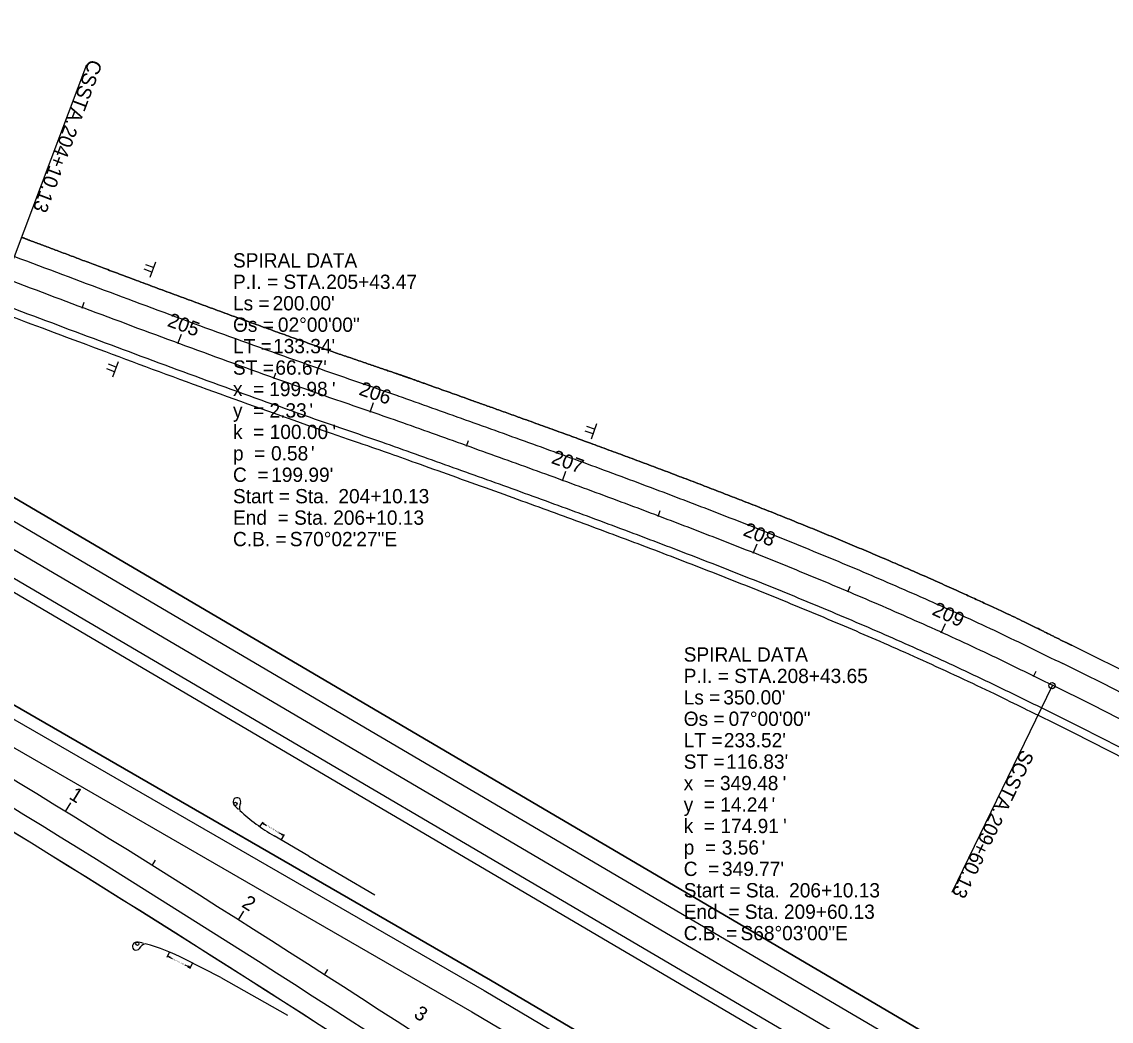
# Model space of a CAD drawing. Extents: x 76539 to 88870, y 518807 to 527554.
# Drawn here: x 86434 to 86968, y 523086 to 523575 of the extents above; entities that cross this region are included whole.
import ezdxf

# ---------------------------------------------------------------- set-up
doc = ezdxf.new("R2010")
doc.units = 0
for name, color, linetype in [('Default', 7, 'Continuous'), ('GE_P_Alignment_100_Cardinal_Points', 7, 'Continuous'), ('GE_P_Alignment_100_Curve_Data', 7, 'Continuous'), ('GE_P_Alignment_100_Stations', 7, 'Continuous'), ('PM_P_Channelizing_Line', 7, 'Continuous'), ('PM_P_Edge_Line', 7, 'Continuous'), ('PM_P_Lane_Line', 7, 'Continuous'), ('PV_P_Shoulder', 7, 'Continuous'), ('RD_P_GR_Lt', 7, 'Continuous'), ('RD_P_GR_Rt', 7, 'Continuous'), ('SC_Scratch1', 7, 'Continuous'), ('SN_P_Signs', 7, 'Continuous'), ('XS_P_Pavt_Surface', 7, 'Continuous')]:
    doc.layers.add(name, color=color, linetype=linetype)

msp = doc.modelspace()

# ---------------------------------------------------------------- linework, layer by layer
at = {"layer": 'Default'}
for points, degree in [([(86434.29, 523469.66), (86442.89, 523466.42), (86474.56, 523454.49), (86527.69, 523434.72), (86580.89, 523415.49), (86612.89, 523404.64), (86621.59, 523401.64)], 2), ([(86430.77, 523460.3), (86446.36, 523454.43), (86477.52, 523442.7), (86524.32, 523425.33), (86571.2, 523408.33), (86602.64, 523397.56), (86618.35, 523392.18)], 3), ([(86426.66, 523449.38), (86442.25, 523443.51), (86473.45, 523431.77), (86520.32, 523414.37), (86567.33, 523397.33), (86598.86, 523386.52), (86614.62, 523381.12)], 3), ([(86421.2, 523433.99), (86429.83, 523430.74), (86461.56, 523418.78), (86514.82, 523398.96), (86568.35, 523379.62), (86600.51, 523368.71), (86609.22, 523365.71)], 3), ([(86621.9, 523401.53), (86628.17, 523399.29), (86649.89, 523391.56), (86689.46, 523377.35), (86720.79, 523365.92), (86754.24, 523353.44), (86787.04, 523340.83), (86819.71, 523327.82), (86852.75, 523314.08), (86883.42, 523300.75), (86921.88, 523283.11), (86942.6, 523272.75), (86948.57, 523269.84)], 2), ([(86618.54, 523392.11), (86629.54, 523388.19), (86651.54, 523380.35), (86684.52, 523368.5), (86717.47, 523356.49), (86750.36, 523344.22), (86783.15, 523331.62), (86815.82, 523318.61), (86848.32, 523305.11), (86880.6, 523291.03), (86912.61, 523276.39), (86933.65, 523266.04), (86944.15, 523260.87)], 3), ([(86614.63, 523381.12), (86625.62, 523377.2), (86647.6, 523369.37), (86680.54, 523357.54), (86713.42, 523345.54), (86746.22, 523333.31), (86778.89, 523320.76), (86811.41, 523307.8), (86843.74, 523294.38), (86875.83, 523280.39), (86907.67, 523265.83), (86928.61, 523255.52), (86939.07, 523250.36)], 3), ([(86609.22, 523365.71), (86615.44, 523363.49), (86636.98, 523355.82), (86676.16, 523341.76), (86707.16, 523330.44), (86740.23, 523318.11), (86772.63, 523305.67), (86804.87, 523292.84), (86837.43, 523279.3), (86867.67, 523266.17), (86905.43, 523248.86), (86925.84, 523238.64), (86931.79, 523235.75)], 3)]:
    msp.add_open_spline(points, degree=degree, dxfattribs=at)
at = {"layer": 'GE_P_Alignment_100_Cardinal_Points'}
for p, q in [((86426.54, 523449.07), (86466.17, 523554.36)), ((86938.93, 523250.06), (86889.8, 523148.86))]:
    msp.add_line(p, q, dxfattribs=at)
msp.add_circle((86938.93, 523250.06), 1.5, dxfattribs=at)
at = {"layer": 'GE_P_Alignment_100_Stations'}
for p, q in [((86463.86, 523435.04), (86464.91, 523437.85)), ((86510.72, 523417.61), (86512.45, 523422.3)), ((86557.72, 523400.55), (86558.73, 523403.37)), ((86604.92, 523384.06), (86606.53, 523388.79)), ((86652.06, 523367.4), (86653.08, 523370.22)), ((86699.09, 523350.41), (86700.8, 523355.1)), ((86745.96, 523332.99), (86747.02, 523335.8)), ((86792.58, 523314.93), (86794.42, 523319.57)), ((86838.85, 523295.98), (86840.02, 523298.74)), ((86884.65, 523275.93), (86886.72, 523280.49)), ((86929.86, 523254.57), (86931.18, 523257.26)), ((86455.66, 523188.45), (86458.29, 523192.71)), ((86498.11, 523162.04), (86499.71, 523164.58)), ((86540.42, 523135.38), (86543.09, 523139.61)), ((86582.57, 523108.49), (86584.19, 523111.01))]:
    msp.add_line(p, q, dxfattribs=at)
at = {"layer": 'PM_P_Channelizing_Line'}
msp.add_arc((81834.27, 515713.3), 8788.35, 54.569749, 58.926203, dxfattribs=at)
at = {"layer": 'PM_P_Edge_Line'}
for p, q in [((86028.65, 523566.61), (87281.21, 522830.81)), ((86016.49, 523545.92), (87269.05, 522810.12)), ((86618.35, 523392.18), (86618.49, 523392.13)), ((86618.35, 523392.18), (86618.49, 523392.13)), ((86618.49, 523392.13), (86618.54, 523392.11)), ((86618.49, 523392.13), (86618.54, 523392.11)), ((86382.45, 523261.25), (86660.77, 523100.7)), ((86944.15, 523260.87), (86944.17, 523260.86)), ((86944.15, 523260.87), (86944.17, 523260.86)), ((86660.77, 523100.7), (86962.34, 522923.05))]:
    msp.add_line(p, q, dxfattribs=at)
for centre, radius, start, end in [((86313.45, 521961.45), 1444.39, 9.23728, 64.10866), ((86313.45, 521961.45), 1444.39, 9.23728, 64.10866), ((86313.45, 521961.45), 1420.39, 9.24998, 64.10866), ((81834.27, 515713.3), 8776.35, 54.569749, 58.926203)]:
    msp.add_arc(centre, radius, start, end, dxfattribs=at)
for points in [[(86430.77, 523460.3), (86446.36, 523454.43), (86477.52, 523442.7), (86524.32, 523425.33), (86571.2, 523408.33), (86602.64, 523397.56), (86618.35, 523392.18)], [(86422.53, 523437.76), (86438.06, 523431.91), (86469.22, 523420.18), (86516.1, 523402.79), (86563.18, 523385.71), (86594.77, 523374.89), (86610.54, 523369.48)], [(86618.54, 523392.11), (86629.54, 523388.19), (86651.54, 523380.35), (86684.52, 523368.5), (86717.47, 523356.49), (86750.36, 523344.22), (86783.15, 523331.62), (86815.82, 523318.61), (86848.32, 523305.11), (86880.6, 523291.03), (86912.61, 523276.39), (86933.65, 523266.04), (86944.15, 523260.87)], [(86610.54, 523369.48), (86621.51, 523365.57), (86643.45, 523357.75), (86676.33, 523345.94), (86709.14, 523333.98), (86741.84, 523321.78), (86774.39, 523309.27), (86806.76, 523296.38), (86838.9, 523283.03), (86870.79, 523269.13), (86902.39, 523254.68), (86923.17, 523244.45), (86933.55, 523239.34)]]:
    msp.add_open_spline(points, degree=3, dxfattribs=at)
at = {"layer": 'PM_P_Lane_Line'}
for p, q in [((86022.57, 523556.26), (87275.13, 522820.47)), ((86614.62, 523381.12), (86614.63, 523381.12)), ((86614.63, 523381.12), (86614.63, 523381.12)), ((86376.45, 523250.86), (86654.78, 523090.3)), ((86939.07, 523250.36), (86939.07, 523250.36)), ((86654.68, 523090.36), (86956.25, 522912.71))]:
    msp.add_line(p, q, dxfattribs=at)
msp.add_arc((86313.45, 521961.45), 1432.72, 9.23728, 64.10866, dxfattribs=at)
at = {"layer": 'PV_P_Shoulder'}
for p, q in [((86033.71, 523575.23), (87286.27, 522839.43)), ((86013.45, 523540.74), (87266.01, 522804.95)), ((86621.59, 523401.64), (86621.79, 523401.57)), ((86621.79, 523401.57), (86621.9, 523401.53)), ((86948.46, 523269.89), (86948.54, 523269.86)), ((86385.49, 523266.43), (86663.82, 523105.87)), ((86663.82, 523105.87), (86965.39, 522928.22))]:
    msp.add_line(p, q, dxfattribs=at)
for centre, radius, start, end in [((86313.45, 521961.45), 1454.39, 32.40267, 64.10866), ((86313.45, 521961.45), 1416.39, 39.00003, 64.10866), ((81834.27, 515713.3), 8766.35, 54.569749, 58.926203)]:
    msp.add_arc(centre, radius, start, end, dxfattribs=at)
at = {"layer": 'RD_P_GR_Lt'}
for p, q in [((86574.85, 523166.55), (86607.18, 523147.56)), ((86531.78, 523107.12), (86514.2, 523116.12))]:
    msp.add_line(p, q, dxfattribs=at)
msp.add_arc((86468.4, 523026.66), 100.51, 62.8901, 74.7951, dxfattribs=at)
at = {"layer": 'RD_P_GR_Rt'}
for p, q in [((86574.85, 523166.55), (86557.83, 523176.55)), ((86531.78, 523107.12), (86564.4, 523088.63))]:
    msp.add_line(p, q, dxfattribs=at)
for centre in [(86538.94, 523192.17), (86490.89, 523123.67)]:
    msp.add_circle(centre, 0.79, dxfattribs=at)
msp.add_arc((86608.74, 523263.21), 100.51, 227.6605, 239.5655, dxfattribs=at)
for centre, major_axis, start_param, end_param in [((86539.64, 523193.24), (0.89, 1.78), 4.797576, 8.898127), ((86546.34, 523190.5), (-2.53, -5.11), 4.770091, 5.435472), ((86546.38, 523198), (-4.61, -9.29), 5.763289, 6.120658), ((86490.37, 523122.51), (-1.03, -1.71), 3.668244, 7.768795), ((86489.96, 523114.27), (5.36, 8.87), 0.162527, 0.519896), ((86496.27, 523118.33), (2.95, 4.88), 0.847713, 1.513095)]:
    msp.add_ellipse(centre, major_axis=major_axis, ratio=0.944544, start_param=start_param, end_param=end_param, dxfattribs=at)
at = {"layer": 'SC_Scratch1'}
for p, q in [((86552.34, 523183.3), (86550.78, 523181.1)), ((86552.05, 523182.89), (86552.85, 523182.18)), ((86553.06, 523182.54), (86552.05, 523182.89)), ((86552.85, 523182.18), (86553.06, 523182.54)), ((86552.95, 523182.36), (86554.23, 523181.62)), ((86561.76, 523177.19), (86560.27, 523178.07)), ((86561.38, 523174.47), (86562.95, 523177.15)), ((86561.66, 523177.01), (86561.87, 523177.37)), ((86562.66, 523176.66), (86561.66, 523177.01)), ((86561.87, 523177.37), (86562.66, 523176.66)), ((86505.56, 523117.13), (86506.59, 523119.63)), ((86505.75, 523117.59), (86506.78, 523117.3)), ((86506.59, 523116.93), (86505.75, 523117.59)), ((86506.78, 523117.3), (86506.59, 523116.93)), ((86506.68, 523117.11), (86508, 523116.44)), ((86515.78, 523112.46), (86514.24, 523113.25)), ((86515.87, 523112.65), (86515.68, 523112.27)), ((86515.68, 523112.27), (86516.71, 523111.98)), ((86516.71, 523111.98), (86515.87, 523112.65)), ((86517.87, 523114.24), (86516.45, 523111.47))]:
    msp.add_line(p, q, dxfattribs=at)
at = {"layer": 'SN_P_Signs'}
for p, q in [((86497.98, 523452.62), (86494.23, 523454.03)), ((86498.82, 523454.87), (86495.08, 523456.27)), ((86499.81, 523457.49), (86497, 523450)), ((86498.4, 523453.74), (86498.4, 523453.74)), ((86480.51, 523406.08), (86476.77, 523407.49)), ((86481.49, 523408.71), (86478.68, 523401.22)), ((86479.67, 523403.84), (86475.92, 523405.24)), ((86480.09, 523404.96), (86480.09, 523404.96)), ((86714.09, 523373.44), (86710.31, 523374.75)), ((86714.87, 523375.71), (86711.09, 523377.01)), ((86715.79, 523378.35), (86713.17, 523370.79)), ((86714.48, 523374.57), (86714.48, 523374.57)), ((86714.48, 523374.57), (86714.48, 523374.57))]:
    msp.add_line(p, q, dxfattribs=at)
at = {"layer": 'XS_P_Pavt_Surface'}
for p, q in [((87286.27, 522839.43), (86033.71, 523575.23)), ((86013.45, 523540.74), (87266.01, 522804.95)), ((86663.82, 523105.87), (86385.49, 523266.43)), ((86962.55, 522929.89), (86663.82, 523105.87))]:
    msp.add_line(p, q, dxfattribs=at)
for centre, radius, start, end in [((86313.45, 521961.45), 1454.39, 32.40267, 64.10866), ((86313.45, 521961.45), 1416.39, 39.00003, 64.10866), ((81834.27, 515713.3), 8766.35, 54.568901, 58.925818)]:
    msp.add_arc(centre, radius, start, end, dxfattribs=at)
for points, degree in [([(86621.59, 523401.64), (86612.89, 523404.64), (86580.89, 523415.49), (86527.69, 523434.72), (86474.56, 523454.49), (86442.89, 523466.42), (86434.29, 523469.66)], 2), ([(86421.2, 523433.99), (86429.83, 523430.74), (86461.56, 523418.78), (86514.82, 523398.96), (86568.35, 523379.62), (86600.51, 523368.71), (86609.22, 523365.71)], 3), ([(86948.57, 523269.84), (86942.6, 523272.75), (86921.88, 523283.11), (86883.42, 523300.75), (86852.75, 523314.08), (86819.71, 523327.82), (86787.04, 523340.83), (86754.24, 523353.44), (86720.79, 523365.92), (86689.46, 523377.35), (86649.89, 523391.56), (86628.17, 523399.29), (86621.9, 523401.53)], 2), ([(86609.22, 523365.71), (86615.44, 523363.49), (86636.98, 523355.82), (86676.16, 523341.76), (86707.16, 523330.44), (86740.23, 523318.11), (86772.63, 523305.67), (86804.87, 523292.84), (86837.43, 523279.3), (86867.67, 523266.17), (86905.43, 523248.86), (86925.84, 523238.64), (86931.79, 523235.75)], 3)]:
    msp.add_open_spline(points, degree=degree, dxfattribs=at)

# ---------------------------------------------------------------- texts
at = {"layer": 'GE_P_Alignment_100_Cardinal_Points'}
for s, rotation, p in [('CS', 249.3741, (86467.39, 523557.31)), (' STA. ', 249.3741, (86463.6, 523547.24)), ('204+10.13', 249.3741, (86455.28, 523525.13)), ('SC', 244.1087, (86924.04, 523219.15)), (' STA. ', 244.1087, (86919.34, 523209.47)), ('209+60.13', 244.1087, (86909.03, 523188.22))]:
    msp.add_text(s, height=7, rotation=rotation, dxfattribs=at).set_placement(p)
at = {"layer": 'GE_P_Alignment_100_Curve_Data'}
for s, p in [('SPIRAL DATA', (86537.73, 523454.89)), ('P.I. = STA. ', (86537.73, 523444.39)), ('205+43.47', (86583.4, 523444.39)), ('Ls = ', (86537.73, 523433.89)), ("200.00'", (86557.13, 523433.89)), ('Θs = ', (86537.73, 523423.39)), ('02°00\'00"', (86559.74, 523423.39)), ('LT = ', (86537.73, 523412.89)), ("133.34'", (86557.36, 523412.89)), ('ST = ', (86537.73, 523402.39)), ("66.67'", (86558.5, 523402.39)), ('x  = ', (86537.73, 523391.89)), ('199.98', (86555.48, 523391.89)), ("'", (86586.2, 523391.89)), ('y  = ', (86537.73, 523381.39)), ('2.33', (86555.63, 523381.39)), ("'", (86575.18, 523381.39)), ('k  = ', (86537.73, 523370.89)), ('100.00', (86555.71, 523370.89)), ("'", (86586.43, 523370.89)), ('p  = ', (86537.73, 523360.39)), ('0.58', (86556.37, 523360.39)), ("'", (86575.92, 523360.39)), ('C  = ', (86537.73, 523349.89)), ("199.99'", (86556.46, 523349.89)), ('Start = Sta. ', (86537.73, 523339.39)), ('204+10.13', (86589.37, 523339.39)), ('End  = Sta. ', (86537.73, 523328.89)), ('206+10.13', (86586.82, 523328.89)), ('C.B. = ', (86537.73, 523318.39)), ('S70°02\'27"E', (86565.55, 523318.39)), ('SPIRAL DATA', (86758.5, 523261.87)), ('P.I. = STA. ', (86758.5, 523251.37)), ('208+43.65', (86804.17, 523251.37)), ('Ls = ', (86758.5, 523240.87)), ("350.00'", (86777.91, 523240.87)), ('Θs = ', (86758.5, 523230.37)), ('07°00\'00"', (86780.51, 523230.37)), ('LT = ', (86758.5, 523219.87)), ("233.52'", (86778.14, 523219.87)), ('ST = ', (86758.5, 523209.37)), ("116.83'", (86779.27, 523209.37)), ('x  = ', (86758.5, 523198.87)), ('349.48', (86776.25, 523198.87)), ("'", (86806.97, 523198.87)), ('y  = ', (86758.5, 523188.37)), ('14.24', (86776.41, 523188.37)), ("'", (86801.54, 523188.37)), ('k  = ', (86758.5, 523177.87)), ('174.91', (86776.49, 523177.87)), ("'", (86807.21, 523177.87)), ('p  = ', (86758.5, 523167.37)), ('3.56', (86777.15, 523167.37)), ("'", (86796.69, 523167.37)), ('C  = ', (86758.5, 523156.87)), ("349.77'", (86777.24, 523156.87)), ('Start = Sta. ', (86758.5, 523146.37)), ('206+10.13', (86810.14, 523146.37)), ('End  = Sta. ', (86758.5, 523135.87)), ('209+60.13', (86807.59, 523135.87)), ('C.B. = ', (86758.5, 523125.37)), ('S68°03\'00"E', (86786.32, 523125.37))]:
    msp.add_text(s, height=7, dxfattribs=at).set_placement(p)
at = {"layer": 'GE_P_Alignment_100_Stations'}
for s, rotation, p in [('205', 339.7779, (86505.13, 523426.33)), ('206', 341.1766, (86598.99, 523392.68)), ('207', 339.9216, (86693.21, 523359.21)), ('208', 338.3231, (86787.14, 523323.81)), ('209', 335.5817, (86879.68, 523285.05)), ('1', 328.2743, (86457, 523194.97)), ('2', 327.6223, (86541.56, 523142.06)), ('3', 326.9703, (86625.8, 523088.01))]:
    msp.add_text(s, height=7, rotation=rotation, dxfattribs=at).set_placement(p)
at = {"layer": 'SC_Scratch1'}
for rotation, p in [(329.5684, (86554.27, 523181.3)), (332.8871, (86508.04, 523116.08))]:
    msp.add_text('LENGTH OF NEED', height=0.5506, rotation=rotation, dxfattribs=at).set_placement(p)

doc.saveas('drawing.dxf')
